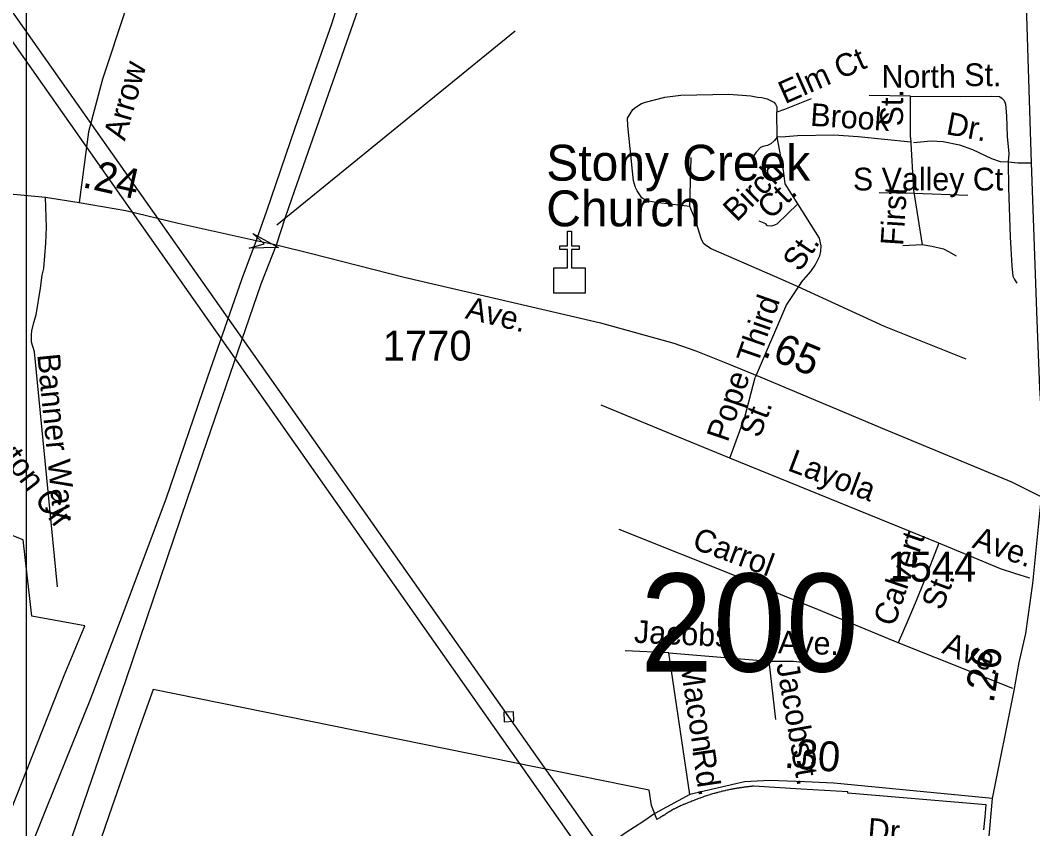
# Model space of a CAD drawing. Extents: x 2220236 to 2384410, y 720751 to 894131.
# Drawn here: x 2329781 to 2334016, y 806939 to 810318 of the extents above; entities that cross this region are included whole.
import ezdxf

# ---------------------------------------------------------------- set-up
doc = ezdxf.new("R2010")
doc.units = 0
doc.layers.add('Default', color=7, linetype='Continuous')

msp = doc.modelspace()

# ---------------------------------------------------------------- linework, layer by layer
at = {"layer": 'Default'}
for p, q in [((2330855, 809463.5), (2331851.7, 810274.4)), ((2333503.7, 810000.6), (2333331.6, 810003.4)), ((2333505, 809827.5), (2333503.7, 810000.6)), ((2332946.1, 809829.8), (2332944.8, 809933.8)), ((2333505, 809827.5), (2333517.5, 809607.7)), ((2332581.4, 809540), (2332587.1, 809743.9)), ((2333517.5, 809607.7), (2333552.7, 809379.9)), ((2333518.3, 809593.8), (2333373.2, 809597.5)), ((2333519.5, 809594.9), (2333744.6, 809587.4)), ((2333552.7, 809379.9), (2333471.8, 809374.8)), ((2333622.4, 808132.9), (2332749.3, 808488.2)), ((2333932, 807525.3), (2333452.9, 807715.5)), ((2332493.3, 807673.8), (2332311.3, 807682)), ((2332581.8, 807081), (2332493.3, 807673.8)), ((2332493.3, 807673.8), (2332911.9, 807638.9)), ((2332911.9, 807638.9), (2332940.3, 807395.3))]:
    msp.add_line(p, q, dxfattribs=at)
for points in [[(2319853.3, 820695.9), (2326592.3, 814719.1), (2333025.8, 805564.5)], [(2333024.4, 805702.5), (2331824.6, 807406.8), (2329674.8, 810458.2), (2329041.4, 811359.1), (2328249.6, 812486.1), (2327790.8, 813138.8), (2326970.6, 814303.4), (2326633.7, 814783.6), (2326625.6, 814795.5), (2319961.3, 820697.1)], [(2329807.7, 816974.9), (2370566.3, 816974.8), (2370566.3, 785046.7), (2329807.6, 785046.7), (2329807.7, 816974.9)], [(2334052.4, 808325.7), (2334066.5, 808455.1), (2334044.7, 808780.9), (2334034.5, 809063.1), (2334010.7, 809722.4), (2333994.8, 810202.7), (2333978.4, 810742.3), (2333976.7, 810869.6), (2333980.1, 810947.1), (2333993, 811039.2), (2334020.4, 811151.2), (2334071.1, 811289.8), (2334459.4, 812339.6), (2334569.5, 812637.4), (2334779.9, 813209.7), (2334807.6, 813321.9), (2334817.9, 813383.5), (2334822.8, 813468.1), (2334821.5, 813577.9), (2334785.5, 813894.3)], [(2330363.5, 811367.6), (2330406.4, 811281.6), (2330424.6, 811222), (2330434.5, 811164.1), (2330439.5, 811109.6), (2330429.6, 811025.2), (2330416.3, 810950.8), (2330125.4, 810072.6), (2330066.8, 809851.8), (2330028.2, 809556.4)], [(2330852.3, 809379), (2330889.9, 809495.1), (2330930.2, 809608.4), (2331088.9, 810060.9), (2331250.2, 810524), (2331392.5, 810919.8), (2331465.9, 811120.8)], [(2331266, 810883.8), (2331082.4, 810301.9), (2330929, 809867.9), (2330810.7, 809520), (2330767.9, 809398)], [(2328232.7, 810123.4), (2328347.8, 810088.6), (2328425.9, 810062.2), (2328517.8, 810018.9), (2328950.7, 809815), (2329109.4, 809738.9), (2329241.6, 809688.4), (2329404.2, 809643), (2329500.3, 809625), (2329618.4, 809603.3), (2329886.7, 809579), (2330028.2, 809556.4), (2330222.5, 809522.6), (2330442.1, 809469.8), (2330767.9, 809398)], [(2332581.4, 809540), (2332439.3, 809556.4), (2332409.2, 809562.2), (2332393, 809567.9), (2332381.1, 809575.9), (2332360.6, 809605.6), (2332354.5, 809619.6), (2332346.3, 809647.5), (2332321.7, 809877.1), (2332321.4, 809908.9), (2332343, 809945.2), (2332355, 809955.3), (2332378.8, 809969.7), (2332396.7, 809975.8), (2332476.5, 809996.7), (2332544.4, 810005.5), (2332744.1, 810009.4), (2332836.2, 810002.6), (2332864.2, 809996.7), (2332882.3, 809995.1), (2332904.4, 809989.2), (2332932.5, 809975.5), (2332940.4, 809967.6), (2332944.7, 809955.8), (2332944.8, 809933.8)], [(2333089.1, 809990.3), (2332977, 809944.6), (2332944.8, 809933.8)], [(2333503.7, 810000.6), (2333714.5, 809999.1), (2333843.5, 810000.6), (2333876.1, 809999.6), (2333886.4, 809992.7), (2333896.7, 809982.3), (2333901.9, 809966.9), (2333905.3, 809918.7), (2333908.8, 809832.6), (2333915.6, 809762), (2333913.2, 809726.7)], [(2332946.1, 809829.8), (2332936.2, 809815.6), (2332920.4, 809801.6), (2332906.5, 809795.4), (2332886.4, 809791.2), (2332876.6, 809787), (2332858.8, 809766.8), (2332848.8, 809752.8)], [(2333505.1, 809808.3), (2333285.1, 809830.9), (2333183.2, 809837.7), (2333032, 809835.6), (2332981.8, 809831.3), (2332946.1, 809829.8)], [(2333032.9, 809551.2), (2332980.1, 809634.1), (2332973.6, 809690.1), (2332946.1, 809829.8)], [(2333516.6, 809806.9), (2333591.1, 809814.6), (2333641.1, 809811), (2333709.3, 809798), (2333763.5, 809778.6), (2333843.5, 809740.9), (2333879.4, 809728), (2333913.2, 809726.7)], [(2333913.2, 809726.7), (2333914.8, 809618.3), (2333921.7, 809411.8), (2333928.5, 809291.3), (2333932, 809248.2), (2333938.9, 809234.5), (2333949.2, 809219)], [(2333913.2, 809726.7), (2333953.5, 809722.4), (2334010.7, 809722.4)], [(2329873.6, 809253), (2329879.3, 809281), (2329888.2, 809387), (2329891.5, 809452.9), (2329886.7, 809579)], [(2333034.2, 809203.6), (2332968.9, 809233.8), (2332671.2, 809363), (2332650.9, 809374.8), (2332638.9, 809384.7), (2332628.6, 809406.5), (2332603.8, 809486.3), (2332581.4, 809540)], [(2333032.9, 809551.2), (2332945.9, 809465.9), (2332932, 809459.7), (2332922, 809457.7), (2332906, 809459.5), (2332899.8, 809467.4), (2332871.8, 809479.1)], [(2333046.5, 809222.1), (2333087.8, 809268.6), (2333105.5, 809294.7), (2333125, 809333.1), (2333128.8, 809353.1), (2333130.5, 809375.2), (2333124.2, 809406.9), (2333032.9, 809551.2)], [(2330767.9, 809398), (2330708.6, 809236.7), (2330564.4, 808826.8), (2330389.8, 808316.1), (2330199.4, 807808), (2330072.4, 807474.6), (2329892.6, 807030), (2329681.9, 806506.8)], [(2330767.9, 809398), (2330852.3, 809379)], [(2329846, 806471), (2329968, 806815.7), (2330224.5, 807561.9), (2330481, 808318.7), (2330789.3, 809217.1), (2330852.3, 809379)], [(2330852.3, 809379), (2330999.1, 809343.1), (2331387.4, 809244.8), (2332041.3, 809092.9), (2332207.6, 809053.8), (2332514.3, 808968.3), (2332607.2, 808936.6), (2332732.4, 808885.9), (2332878.1, 808825.7), (2333396.2, 808608.8), (2333927.1, 808388.6), (2334052.4, 808325.7)], [(2333696.9, 809331.9), (2333664.5, 809350.7), (2333643.9, 809361), (2333624.9, 809366.1), (2333594, 809373), (2333552.7, 809379.9)], [(2329937.6, 807950.1), (2329841.1, 808932.7), (2329828.7, 808972.6), (2329828.2, 809002.6), (2329830.1, 809020.5), (2329837.7, 809054.6), (2329847.4, 809086.8), (2329866.2, 809198.8), (2329873.6, 809253)], [(2333046.5, 809222.1), (2332985.4, 809130.6), (2332855.2, 808824.8)], [(2333737.4, 808901), (2333396.2, 809038.7), (2333034.3, 809203.8)], [(2332749.3, 808488.2), (2332811.3, 808659.3), (2332855.2, 808824.8)], [(2332749.3, 808488.2), (2332531.1, 808577.5), (2332211.3, 808709)], [(2329721.2, 806962.3), (2329964.5, 807579.1), (2330048, 807779.5), (2330051.2, 807787), (2329829.8, 807827.4), (2329793.8, 808146.9), (2329276, 808349.8)], [(2329721.2, 806962.3), (2329964.5, 807579.1), (2330048, 807779.5), (2330051.2, 807787), (2329829.8, 807827.4), (2329793.8, 808146.9), (2329276, 808349.8)], [(2333847.2, 807065.2), (2333937.6, 807516.4), (2333958.6, 807632.9), (2333986.2, 807755), (2334016.3, 807963.1), (2334052.4, 808325.7)], [(2333452.9, 807715.5), (2333120.1, 807854.1), (2332977.3, 807910.9), (2332803.6, 807983.1), (2332286, 808189.3)], [(2333622.4, 808132.9), (2333559.6, 807970.2), (2333528.6, 807891.1), (2333492.5, 807808.4), (2333452.9, 807715.5)], [(2334003.4, 807985.7), (2333940.6, 808005.5), (2333880.4, 808024.5), (2333770.3, 808070.9), (2333622.4, 808132.9)], [(2332911.9, 807638.9), (2333015.2, 807638.9), (2333159.6, 807621.7)], [(2333811, 806934.4), (2333816, 806987.8), (2333821, 807038.2), (2333242, 807086.6), (2333241.8, 807092.2), (2333046.8, 807104.2), (2332849, 807116.4), (2332846, 807116.2), (2332843.5, 807115.9), (2332841, 807115.7), (2332838.5, 807115.4), (2332836, 807115.2), (2332833.5, 807114.9), (2332831, 807114.7), (2332828.5, 807114.4), (2332826, 807114.1), (2332823.5, 807113.8), (2332818.8, 807113.2), (2332816.2, 807112.9), (2332813.8, 807112.6), (2332811.2, 807112.3), (2332808.8, 807111.9), (2332806.2, 807111.6), (2332803.8, 807111.3), (2332801.2, 807110.9), (2332798.8, 807110.6), (2332796.2, 807110.2), (2332791.5, 807109.4), (2332789, 807109.1), (2332786.5, 807108.7), (2332784, 807108.3), (2332781.5, 807107.9), (2332779, 807107.5), (2332776.5, 807107.1), (2332771.8, 807106.2), (2332769.2, 807105.8), (2332766.8, 807105.3), (2332764.2, 807104.9), (2332761.8, 807104.4), (2332757, 807103.4), (2332754.5, 807102.9), (2332752, 807102.5), (2332749.5, 807102), (2332744.8, 807100.9), (2332739.8, 807099.9), (2332737.2, 807099.4), (2332732.5, 807098.3), (2332730, 807097.8), (2332727.5, 807097.2), (2332722.8, 807096.1), (2332720.2, 807095.5), (2332717.8, 807094.9), (2332713, 807093.7), (2332710.5, 807093.1), (2332705.8, 807091.9), (2332703.2, 807091.2), (2332698.5, 807090), (2332696, 807089.3), (2332691.2, 807088), (2332688.8, 807087.4), (2332684, 807086), (2332681.5, 807085.3), (2332676.8, 807083.9), (2332672, 807082.5), (2332667.2, 807081.1), (2332664.8, 807080.3), (2332655.2, 807077.3), (2332650.5, 807075.8), (2332645.8, 807074.2), (2332641, 807072.6), (2332636.2, 807071), (2332631.5, 807069.3), (2332627, 807067.7), (2332624.5, 807066.8), (2332619.8, 807065.1), (2332615.2, 807063.4), (2332612.8, 807062.5), (2332608.2, 807060.7), (2332605.8, 807059.8), (2332601.2, 807058), (2332598.8, 807057.1), (2332594.2, 807055.2), (2332589.5, 807053.3), (2332585, 807051.4), (2332580.2, 807049.5), (2332573.5, 807046.4), (2332570.2, 807045.1), (2332566.5, 807043.5), (2332563.5, 807042.3), (2332557.2, 807040.3), (2332554.2, 807039.2), (2332552, 807037.8), (2332547.2, 807036.2), (2332542.8, 807034.1), (2332538.2, 807032.1), (2332533.8, 807029.9), (2332531.5, 807028.8), (2332527, 807026.6), (2332524.8, 807025.5), (2332522.5, 807024.3), (2332520.2, 807023.2), (2332518, 807022), (2332515.8, 807020.9), (2332513.2, 807019.8), (2332509, 807017.4), (2332503, 807013.9), (2332500.8, 807012.6), (2332497.5, 807010.6), (2332493.8, 807008.2), (2332490.2, 807005.9), (2332486.2, 807003.4), (2332482.2, 807000.9), (2332480, 806999.7), (2332475.8, 806995.2), (2332473.2, 806995.4), (2332469.8, 806993.1), (2332467.5, 806991.8), (2332465.2, 806990.4), (2332462.8, 806988.9), (2332460.5, 806987.6), (2332457.8, 806986.1), (2332455.5, 806984.6), (2332453, 806983.2), (2332450.2, 806981.8), (2332448, 806980.2), (2332445.5, 806978.8), (2332443.2, 806977.4), (2332442.8, 806978.4), (2332421.5, 807035.8), (2332411.5, 807099.7), (2330336.5, 807520.9), (2330284.8, 807372.6), (2330152.2, 806992.1), (2330086, 806801.9)], [(2333811, 806934.4), (2333816, 806987.8), (2333821, 807038.2), (2333242, 807086.6), (2333241.8, 807092.2), (2333046.8, 807104.2), (2332849, 807116.4), (2332846, 807116.2), (2332843.5, 807115.9), (2332841, 807115.7), (2332838.5, 807115.4), (2332836, 807115.2), (2332833.5, 807114.9), (2332831, 807114.7), (2332828.5, 807114.4), (2332826, 807114.1), (2332823.5, 807113.8), (2332818.8, 807113.2), (2332816.2, 807112.9), (2332813.8, 807112.6), (2332811.2, 807112.3), (2332808.8, 807111.9), (2332806.2, 807111.6), (2332803.8, 807111.3), (2332801.2, 807110.9), (2332798.8, 807110.6), (2332796.2, 807110.2), (2332791.5, 807109.4), (2332789, 807109.1), (2332786.5, 807108.7), (2332784, 807108.3), (2332781.5, 807107.9), (2332779, 807107.5), (2332776.5, 807107.1), (2332771.8, 807106.2), (2332769.2, 807105.8), (2332766.8, 807105.3), (2332764.2, 807104.9), (2332761.8, 807104.4), (2332757, 807103.4), (2332754.5, 807102.9), (2332752, 807102.5), (2332749.5, 807102), (2332744.8, 807100.9), (2332739.8, 807099.9), (2332737.2, 807099.4), (2332732.5, 807098.3), (2332730, 807097.8), (2332727.5, 807097.2), (2332722.8, 807096.1), (2332720.2, 807095.5), (2332717.8, 807094.9), (2332713, 807093.7), (2332710.5, 807093.1), (2332705.8, 807091.9), (2332703.2, 807091.2), (2332698.5, 807090), (2332696, 807089.3), (2332691.2, 807088), (2332688.8, 807087.4), (2332684, 807086), (2332681.5, 807085.3), (2332676.8, 807083.9), (2332672, 807082.5), (2332667.2, 807081.1), (2332664.8, 807080.3), (2332655.2, 807077.3), (2332650.5, 807075.8), (2332645.8, 807074.2), (2332641, 807072.6), (2332636.2, 807071), (2332631.5, 807069.3), (2332627, 807067.7), (2332624.5, 807066.8), (2332619.8, 807065.1), (2332615.2, 807063.4), (2332612.8, 807062.5), (2332608.2, 807060.7), (2332605.8, 807059.8), (2332601.2, 807058), (2332598.8, 807057.1), (2332594.2, 807055.2), (2332589.5, 807053.3), (2332585, 807051.4), (2332580.2, 807049.5), (2332573.5, 807046.4), (2332570.2, 807045.1), (2332566.5, 807043.5), (2332563.5, 807042.3), (2332557.2, 807040.3), (2332554.2, 807039.2), (2332552, 807037.8), (2332547.2, 807036.2), (2332542.8, 807034.1), (2332538.2, 807032.1), (2332533.8, 807029.9), (2332531.5, 807028.8), (2332527, 807026.6), (2332524.8, 807025.5), (2332522.5, 807024.3), (2332520.2, 807023.2), (2332518, 807022), (2332515.8, 807020.9), (2332513.2, 807019.8), (2332509, 807017.4), (2332503, 807013.9), (2332500.8, 807012.6), (2332497.5, 807010.6), (2332493.8, 807008.2), (2332490.2, 807005.9), (2332486.2, 807003.4), (2332482.2, 807000.9), (2332480, 806999.7), (2332475.8, 806995.2), (2332473.2, 806995.4), (2332469.8, 806993.1), (2332467.5, 806991.8), (2332465.2, 806990.4), (2332462.8, 806988.9), (2332460.5, 806987.6), (2332457.8, 806986.1), (2332455.5, 806984.6), (2332453, 806983.2), (2332450.2, 806981.8), (2332448, 806980.2), (2332445.5, 806978.8), (2332443.2, 806977.4), (2332442.8, 806978.4), (2332421.5, 807035.8), (2332411.5, 807099.7), (2330336.5, 807520.9), (2330284.8, 807372.6), (2330152.2, 806992.1), (2330086, 806801.9)], [(2331805.5, 807386), (2331845.4, 807387.7), (2331843.8, 807427.6), (2331803.8, 807426), (2331805.5, 807386)], [(2333847.2, 807065.2), (2333183.7, 807128.9), (2333062.3, 807135.2), (2332916.6, 807140.5), (2332810, 807135.2), (2332581.8, 807081), (2332434.5, 807001.6), (2332384.9, 806967), (2332315.5, 806922.3), (2331245.5, 806176.5)], [(2333820.8, 805599.9), (2333819.3, 805681), (2333814.2, 806343.7), (2333821, 806670.7), (2333826.2, 806829.1), (2333847.2, 807065.2)]]:
    msp.add_lwpolyline(points, dxfattribs=at)
for points in [[(2332013, 809283.7), (2332069.9, 809283.8), (2332069.9, 809359.9), (2332037.9, 809359.9), (2332037.9, 809375.9), (2332069.9, 809375.9), (2332069.9, 809436), (2332086, 809436), (2332086, 809375.9), (2332118, 809375.9), (2332118, 809359.9), (2332086, 809359.9), (2332086, 809283.8), (2332143.6, 809283.7), (2332143.6, 809177.2), (2332013, 809177.2)], [(2330754.2, 809427.3), (2330861, 809368.5), (2330739.1, 809366), (2330801.8, 809383.1)]]:
    msp.add_lwpolyline(points, close=True, dxfattribs=at)

# ---------------------------------------------------------------- texts
for s, height, rotation, p in [('Elm Ct', 95, 23.9724, (2332979.2, 809966.8)), ('Arrow', 95, 74.0656, (2330218.7, 809811)), ('St.', 95, 359.7767, (2333729.1, 810043.3)), ('St.', 95, 89.4705, (2333472.7, 809874.5)), ('Brook', 95, 356.1816, (2333083.3, 809877.4)), ('Dr.', 95, 349.2089, (2333649.5, 809842.8)), ('.24', 125, 347.1758, (2330036.8, 809621.3)), ('Birch', 95, 44.4707, (2332777.1, 809471.9)), ('Ct.', 95, 44.4707, (2332920.2, 809481.3)), ('First', 95, 86.2482, (2333473.7, 809373.8)), ('St.', 95, 55.8553, (2333041.4, 809262.5)), ('Ave.', 95, 346.3875, (2331638.4, 809072.9)), ('Third', 95, 70.7076, (2332864.2, 808875.3)), ('.65', 125, 337.4771, (2332878.9, 808916.8)), ('Ben Layton Cir', 95, 307.4848, (2329424.7, 808852.1)), ('Banner Way', 95, 275.6035, (2329852.1, 808920.8)), ('Pope', 95, 71.2869, (2332739.3, 808551.3)), ('St.', 95, 68.9851, (2332872.9, 808568)), ('Layola', 95, 339.195, (2332985.6, 808438.1)), ('Carrol', 95, 339.5734, (2332586.3, 808112.4)), ('Calvert', 95, 71.2869, (2333436.3, 807779.9)), ('Ave.', 95, 340.4573, (2333758, 808115)), ('St.', 95, 68.9851, (2333636.1, 807847.2)), ('Jacobs', 95, 357.4206, (2332346.8, 807716.2)), ('Ave.', 95, 358.3137, (2332949.7, 807672.1)), ('Ave.', 95, 338.3308, (2333631.2, 807674.7)), ('.26', 125, 80.6243, (2333851.3, 807460.5)), ('Macon', 95, 278.4911, (2332540.2, 807630.6)), ('Jacobs', 95, 279.986, (2332942.6, 807626.4)), ('.30', 125, 355.3998, (2332973.6, 807193.9)), ('St.', 95, 279.986, (2333005.3, 807267.1)), ('Rd.', 95, 278.4911, (2332591.3, 807266.5)), ('Dr.', 95, 355.3998, (2333322.3, 806889.6))]:
    msp.add_text(s, height=height, rotation=rotation, dxfattribs=at).set_placement(p)
for s, height, p in [('North', 95, (2333383.3, 810035.9)), ('Stony Creek', 150, (2331981.2, 809647.8)), ('S Valley Ct', 95, (2333263.7, 809606.9)), ('Church', 150, (2331981.2, 809456.8)), ('1770', 125, (2331297.1, 808895.8)), ('1544', 125, (2333407.8, 807971.7)), ('200', 410.1, (2332373.2, 807595.3))]:
    msp.add_text(s, height=height, dxfattribs=at).set_placement(p)

doc.saveas('drawing.dxf')
